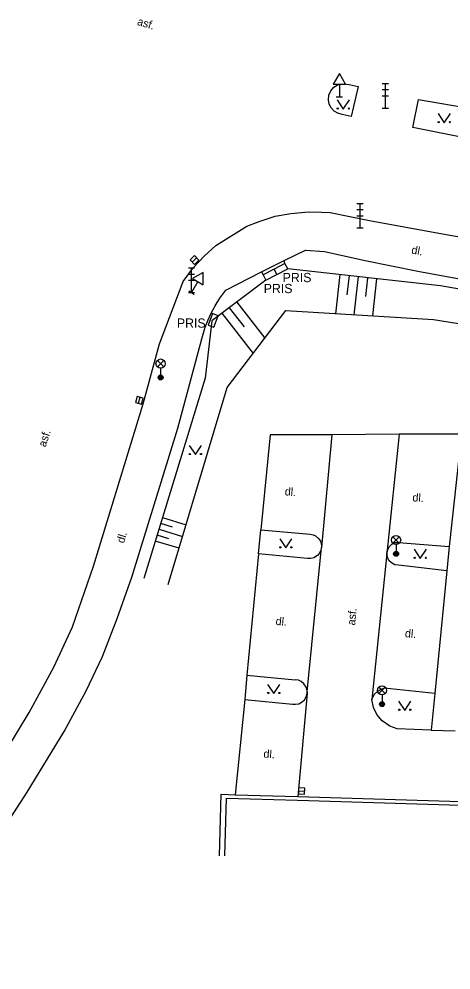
# Model space of a CAD drawing. Extents: x -598341 to -594502, y -1162301 to -1161406.
# Drawn here: x -598037.9 to -598002.8, y -1161565.6 to -1161488.4 of the extents above; entities that cross this region are included whole.
import ezdxf

# ---------------------------------------------------------------- set-up
doc = ezdxf.new("R2010")
doc.units = 0
for name, color, linetype in [('Vrstva 10', 7, 'Continuous'), ('Vrstva 11', 7, 'Continuous'), ('Vrstva 14', 7, 'Continuous'), ('Vrstva 15', 7, 'Continuous'), ('Vrstva 24', 7, 'Continuous'), ('Vrstva 27', 7, 'Continuous'), ('Vrstva 33', 7, 'Continuous'), ('Vrstva 34', 7, 'Continuous'), ('Vrstva 36', 7, 'Continuous'), ('Vrstva 40', 7, 'Continuous'), ('Vrstva 41', 7, 'Continuous'), ('Vrstva 7', 7, 'Continuous')]:
    doc.layers.add(name, color=color, linetype=linetype)

msp = doc.modelspace()

# ---------------------------------------------------------------- linework, layer by layer
at = {"layer": 'Vrstva 10'}
for p, q in [((-598005.91, -1161497.18), (-598005.43, -1161494.88)), ((-598005.43, -1161494.88), (-597996.85, -1161496.39)), ((-598000.54, -1161498.25), (-598005.91, -1161497.18)), ((-598017.49, -1161522.14), (-598018.24, -1161529.85)), ((-598012.47, -1161522.12), (-598017.49, -1161522.14)), ((-598007.02, -1161522.08), (-598012.47, -1161522.12)), ((-598001.97, -1161522.08), (-598007.02, -1161522.08)), ((-598002.17, -1161524.03), (-598002.94, -1161531.19)), ((-598018.24, -1161529.85), (-598014.25, -1161530.19)), ((-598007.07, -1161530.87), (-598002.94, -1161531.19)), ((-598018.43, -1161531.81), (-598019.38, -1161541.64)), ((-598014.45, -1161532.17), (-598018.43, -1161531.81)), ((-598003.13, -1161533.19), (-598007.05, -1161532.72)), ((-598003.13, -1161533.19), (-598004.12, -1161543.14)), ((-598019.38, -1161541.64), (-598015.47, -1161542.03)), ((-598004.12, -1161543.14), (-598008.23, -1161542.72)), ((-598019.55, -1161543.63), (-598020.34, -1161551.36)), ((-598019.55, -1161543.63), (-598015.69, -1161544)), ((-598004.41, -1161546.11), (-598007.16, -1161546)), ((-598004.41, -1161546.11), (-598002.45, -1161546.17))]:
    msp.add_line(p, q, dxfattribs=at)
for points in [[(-598011.65, -1161496.1), (-598012, -1161496.01), (-598012.28, -1161495.85), (-598012.54, -1161495.57), (-598012.69, -1161495.26), (-598012.76, -1161494.92), (-598012.72, -1161494.55), (-598012.57, -1161494.19), (-598012.31, -1161493.88), (-598011.97, -1161493.68), (-598011.47, -1161493.61), (-598011.06, -1161493.67)], [(-598011.06, -1161493.67), (-598010.35, -1161493.83), (-598010.9, -1161496.28), (-598011.65, -1161496.1)], [(-598024.56, -1161509.67), (-598023.75, -1161508.56), (-598022.87, -1161507.61), (-598021.9, -1161506.76), (-598019.39, -1161505.19), (-598018.38, -1161504.8), (-598017.09, -1161504.37), (-598015.82, -1161504.14), (-598014.37, -1161504.02), (-598013.31, -1161504.04), (-598012.62, -1161504.08), (-598009.41, -1161504.71), (-598003.49, -1161505.8), (-597999.67, -1161506.48)], [(-598031.85, -1161532.79), (-598027.82, -1161519.62), (-598026.5, -1161514.73), (-598024.56, -1161509.67)], [(-598014.25, -1161530.19), (-598013.99, -1161530.25), (-598013.8, -1161530.34), (-598013.53, -1161530.57), (-598013.41, -1161530.78), (-598013.33, -1161531.06), (-598013.32, -1161531.28)], [(-598007.98, -1161531.64), (-598007.95, -1161531.49), (-598007.8, -1161531.21), (-598007.6, -1161531.02), (-598007.3, -1161530.89), (-598007.07, -1161530.87)], [(-598013.32, -1161531.28), (-598013.37, -1161531.51), (-598013.49, -1161531.73), (-598013.66, -1161531.93), (-598013.94, -1161532.11), (-598014.2, -1161532.18), (-598014.45, -1161532.17)], [(-598008.01, -1161531.78), (-598007.98, -1161531.64)], [(-598007.05, -1161532.72), (-598007.36, -1161532.68), (-598007.63, -1161532.54), (-598007.84, -1161532.33), (-598007.97, -1161532.07), (-598008.01, -1161531.81), (-598008.01, -1161531.78)], [(-598050.45, -1161563.43), (-598046.96, -1161559.29), (-598043.32, -1161554.38), (-598039.96, -1161549.39), (-598037.09, -1161544.69), (-598035.08, -1161541.01), (-598033.56, -1161537.74), (-598031.85, -1161532.79)], [(-598014.5, -1161543.14), (-598014.49, -1161542.9), (-598014.56, -1161542.64), (-598014.75, -1161542.35), (-598014.97, -1161542.16), (-598015.19, -1161542.07), (-598015.47, -1161542.03)], [(-598015.69, -1161544), (-598015.44, -1161544.02), (-598015.17, -1161543.97), (-598014.88, -1161543.82), (-598014.7, -1161543.65), (-598014.57, -1161543.42), (-598014.5, -1161543.14)], [(-598009.22, -1161543.62), (-598009.04, -1161543.23), (-598008.72, -1161542.92), (-598008.44, -1161542.77), (-598008.23, -1161542.72)], [(-598007.16, -1161546), (-598007.76, -1161545.8), (-598008.38, -1161545.37), (-598008.82, -1161544.84), (-598009.09, -1161544.27), (-598009.22, -1161543.62)]]:
    msp.add_lwpolyline(points, dxfattribs=at)
at = {"layer": 'Vrstva 11'}
for p, q in [((-598018.19, -1161508.89), (-598016.35, -1161507.98)), ((-598012.47, -1161522.12), (-598013.32, -1161531.28)), ((-598007.02, -1161522.08), (-598008.01, -1161531.78)), ((-598018.43, -1161531.81), (-598018.24, -1161529.85)), ((-598014.49, -1161543), (-598013.32, -1161531.28)), ((-598008.01, -1161531.78), (-598009.22, -1161543.62)), ((-598002.94, -1161531.19), (-598003.13, -1161533.19)), ((-598019.38, -1161541.64), (-598019.55, -1161543.63)), ((-598004.12, -1161543.14), (-598004.41, -1161546.11))]:
    msp.add_line(p, q, dxfattribs=at)
for points in [[(-598016.35, -1161507.98), (-598014.61, -1161507.12), (-598013.07, -1161507.25)], [(-598013.07, -1161507.25), (-598009.78, -1161507.98), (-598005.49, -1161508.83), (-598001.07, -1161509.66), (-597997.29, -1161510.3), (-597992.79, -1161510.97), (-597987.22, -1161511.73), (-597981.34, -1161512.37), (-597977.31, -1161512.94), (-597973.37, -1161513.39), (-597969.59, -1161513.69), (-597965.98, -1161513.92), (-597963.16, -1161514.01), (-597960.84, -1161514.03)], [(-598016.29, -1161508.21), (-598016.35, -1161507.98)], [(-598021.1, -1161510.38), (-598018.19, -1161508.89)], [(-598018.19, -1161508.89), (-598018.07, -1161509.13)], [(-598023.04, -1161514.34), (-598022.77, -1161513.39), (-598022.54, -1161512.78), (-598022.29, -1161512.25), (-598021.97, -1161511.65), (-598021.58, -1161511.04), (-598021.1, -1161510.38)], [(-598028.75, -1161533.7), (-598025, -1161521.59), (-598023.04, -1161514.34)], [(-598048.05, -1161565.6), (-598045.02, -1161562.04), (-598040.83, -1161556.65), (-598037.24, -1161551.17), (-598034.23, -1161546.23), (-598032.45, -1161542.93), (-598031.11, -1161540.13), (-598031.11, -1161540.13), (-598029.92, -1161537.05), (-598028.75, -1161533.7)], [(-598014.5, -1161543.14), (-598015.25, -1161551.51)], [(-598014.49, -1161543), (-598014.5, -1161543.14)]]:
    msp.add_lwpolyline(points, dxfattribs=at)
at = {"layer": 'Vrstva 14'}
for p, q in [((-598003.64, -1161510.02), (-598016.06, -1161508.65)), ((-598017.84, -1161509.57), (-598022.23, -1161512.87)), ((-597995.58, -1161511.45), (-598003.64, -1161510.02)), ((-598022.23, -1161512.87), (-598022.78, -1161517.53)), ((-598022.78, -1161517.53), (-598027.76, -1161533.81))]:
    msp.add_line(p, q, dxfattribs=at)
msp.add_lwpolyline([(-598025.78, -1161534.3), (-598020.99, -1161518.28), (-598016.22, -1161512.04), (-598004.23, -1161512.77), (-597992.67, -1161514.6), (-597968.39, -1161517.52), (-597961.27, -1161518.23)], dxfattribs=at)
at = {"layer": 'Vrstva 15'}
for p, q in [((-598011.82, -1161509.12), (-598012.17, -1161512.29)), ((-598011.07, -1161509.2), (-598011.25, -1161510.76)), ((-598010.33, -1161509.28), (-598010.68, -1161512.38)), ((-598009.58, -1161509.37), (-598009.75, -1161510.89)), ((-598008.84, -1161509.45), (-598009.18, -1161512.47)), ((-598020.21, -1161511.36), (-598017.94, -1161514.29)), ((-598021.42, -1161512.26), (-598018.88, -1161515.52)), ((-598020.82, -1161511.81), (-598019.62, -1161513.35)), ((-598025.43, -1161529.62), (-598026.39, -1161529.33)), ((-598026.24, -1161528.85), (-598024.32, -1161529.43)), ((-598026.53, -1161529.8), (-598024.61, -1161530.39)), ((-598024.9, -1161531.35), (-598026.83, -1161530.76)), ((-598025.72, -1161530.58), (-598026.68, -1161530.28))]:
    msp.add_line(p, q, dxfattribs=at)
at = {"layer": 'Vrstva 24'}
for points in [[(-598016.948, -1161509.112), (-598016.061, -1161508.651), (-598016.291, -1161508.207), (-598017.178, -1161508.668)], [(-598017.838, -1161509.572), (-598016.951, -1161509.111), (-598017.181, -1161508.667), (-598018.068, -1161509.128)], [(-598022.063, -1161513.396), (-598021.709, -1161512.46), (-598022.177, -1161512.283), (-598022.531, -1161513.219)]]:
    msp.add_lwpolyline(points, close=True, dxfattribs=at)
at = {"layer": 'Vrstva 27'}
for p, q in [((-598023.828, -1161508.106), (-598023.472, -1161507.754)), ((-598028.196, -1161519.561), (-598028.065, -1161519.079)), ((-598015.19, -1161551.05), (-598014.69, -1161551.07))]:
    msp.add_line(p, q, dxfattribs=at)
for points in [[(-598023.653, -1161508.284), (-598023.297, -1161507.932), (-598023.648, -1161507.576), (-598024.004, -1161507.928)], [(-598027.955, -1161519.627), (-598027.823, -1161519.145), (-598028.306, -1161519.013), (-598028.437, -1161519.496)], [(-598015.2, -1161551.3), (-598014.7, -1161551.32), (-598014.68, -1161550.82), (-598015.18, -1161550.8)]]:
    msp.add_lwpolyline(points, close=True, dxfattribs=at)
at = {"layer": 'Vrstva 33'}
for p, q in [((-598008.38, -1161493.59), (-598007.88, -1161493.59)), ((-598008.13, -1161495.59), (-598008.13, -1161493.59)), ((-598008.38, -1161494.09), (-598007.88, -1161494.09)), ((-598008.38, -1161494.59), (-598007.88, -1161494.59)), ((-598008.38, -1161495.59), (-598007.88, -1161495.59)), ((-598010.44, -1161503.33), (-598009.94, -1161503.33)), ((-598010.44, -1161503.83), (-598009.94, -1161503.83)), ((-598010.19, -1161505.33), (-598010.19, -1161503.33)), ((-598010.44, -1161504.33), (-598009.94, -1161504.33)), ((-598010.44, -1161505.33), (-598009.94, -1161505.33)), ((-598024.14, -1161508.57), (-598023.64, -1161508.57)), ((-598023.89, -1161510.57), (-598023.89, -1161508.57)), ((-598024.14, -1161509.07), (-598023.64, -1161509.07)), ((-598024.14, -1161509.57), (-598023.64, -1161509.57)), ((-598024.14, -1161510.57), (-598023.64, -1161510.57)), ((-598026.665, -1161516.61), (-598026.135, -1161516.08)), ((-598026.665, -1161516.08), (-598026.135, -1161516.61)), ((-598026.4, -1161516.72), (-598026.4, -1161517.47)), ((-598007.525, -1161530.94), (-598006.995, -1161530.41)), ((-598007.525, -1161530.41), (-598006.995, -1161530.94)), ((-598007.26, -1161531.05), (-598007.26, -1161531.8)), ((-598008.665, -1161543.15), (-598008.135, -1161542.62)), ((-598008.665, -1161542.62), (-598008.135, -1161543.15)), ((-598008.4, -1161543.26), (-598008.4, -1161544.01))]:
    msp.add_line(p, q, dxfattribs=at)
for centre, radius in [((-598026.4, -1161516.345), 0.375), ((-598026.4, -1161517.47), 0.2), ((-598026.4, -1161517.47), 0.145), ((-598026.4, -1161517.47), 0.0876), ((-598007.26, -1161530.675), 0.375), ((-598007.26, -1161531.8), 0.2), ((-598007.26, -1161531.8), 0.145), ((-598007.26, -1161531.8), 0.0876), ((-598008.4, -1161542.885), 0.375), ((-598008.4, -1161544.01), 0.2), ((-598008.4, -1161544.01), 0.145), ((-598008.4, -1161544.01), 0.0876)]:
    msp.add_circle(centre, radius, dxfattribs=at)
at = {"layer": 'Vrstva 34'}
for p, q in [((-598011.87, -1161493.652), (-598011.87, -1161494.67)), ((-598012.12, -1161494.67), (-598011.62, -1161494.67)), ((-598023.381, -1161509.688), (-598023.89, -1161510.57)), ((-598024.107, -1161510.445), (-598023.673, -1161510.695))]:
    msp.add_line(p, q, dxfattribs=at)
for points in [[(-598012.37, -1161493.652), (-598011.37, -1161493.652), (-598011.87, -1161492.786)], [(-598023.814, -1161509.438), (-598022.948, -1161509.938), (-598022.948, -1161508.938)]]:
    msp.add_lwpolyline(points, close=True, dxfattribs=at)
at = {"layer": 'Vrstva 36'}
for points in [[(-598012.05, -1161494.92), (-598011.55, -1161495.67), (-598011.05, -1161494.92)], [(-598003.84, -1161496.03), (-598003.34, -1161496.78), (-598002.84, -1161496.03)], [(-598024.07, -1161522.99), (-598023.57, -1161523.74), (-598023.07, -1161522.99)], [(-598016.72, -1161530.57), (-598016.22, -1161531.32), (-598015.72, -1161530.57)], [(-598005.79, -1161531.42), (-598005.29, -1161532.17), (-598004.79, -1161531.42)], [(-598017.7, -1161542.4), (-598017.2, -1161543.15), (-598016.7, -1161542.4)], [(-598007.05, -1161543.76), (-598006.55, -1161544.51), (-598006.05, -1161543.76)]]:
    msp.add_lwpolyline(points, dxfattribs=at)
for centre in [(-598012, -1161495.62), (-598011.101, -1161495.62), (-598003.79, -1161496.73), (-598002.891, -1161496.73), (-598024.02, -1161523.69), (-598023.121, -1161523.69), (-598016.67, -1161531.27), (-598015.77, -1161531.27), (-598005.74, -1161532.119), (-598004.84, -1161532.119), (-598017.65, -1161543.1), (-598016.751, -1161543.1), (-598007, -1161544.46), (-598006.101, -1161544.46)]:
    msp.add_circle(centre, 0.05, dxfattribs=at)
at = {"layer": 'Vrstva 7'}
for points in [[(-598021.62, -1161556.33), (-598021.48, -1161551.33), (-598020.34, -1161551.36)], [(-598021.17, -1161556.34), (-598021.04, -1161551.64), (-598015.26, -1161551.81), (-597979.96, -1161552.89), (-597946.54, -1161553.9)], [(-598020.34, -1161551.36), (-598015.25, -1161551.51)], [(-598015.25, -1161551.51), (-597979.95, -1161552.59), (-597946.53, -1161553.6)]]:
    msp.add_lwpolyline(points, dxfattribs=at)

# ---------------------------------------------------------------- texts
at = {"layer": 'Vrstva 40'}
for s, height, rotation, p in [('asf.', 0.65, 343.19521, (-598028.35, -1161488.82)), ('dl.', 0.65, 349.38795, (-598006.05, -1161507.4)), ('asf.', 0.65, 72.04641, (-598035.75, -1161523.17)), (' dl.', 0.6499, 355.12942, (-598016.57, -1161527.02)), (' dl.', 0.65, 355.56947, (-598006.19, -1161527.51)), ('dl.', 0.65, 72.79426, (-598029.39, -1161530.98)), (' asf.', 0.6499, 84.18021, (-598010.62, -1161537.87)), (' dl.', 0.6499, 355.12942, (-598017.31, -1161537.55)), (' dl.', 0.6499, 355.12942, (-598006.8, -1161538.54)), (' dl.', 0.6499, 355.12942, (-598018.3, -1161548.32))]:
    msp.add_text(s, height=height, rotation=rotation, dxfattribs=at).set_placement(p)
at = {"layer": 'Vrstva 41'}
for p in [(-598016.48, -1161509.73), (-598018.02, -1161510.62), (-598025.08, -1161513.43)]:
    msp.add_text('PRIS', height=0.75, dxfattribs=at).set_placement(p)

doc.saveas('drawing.dxf')
